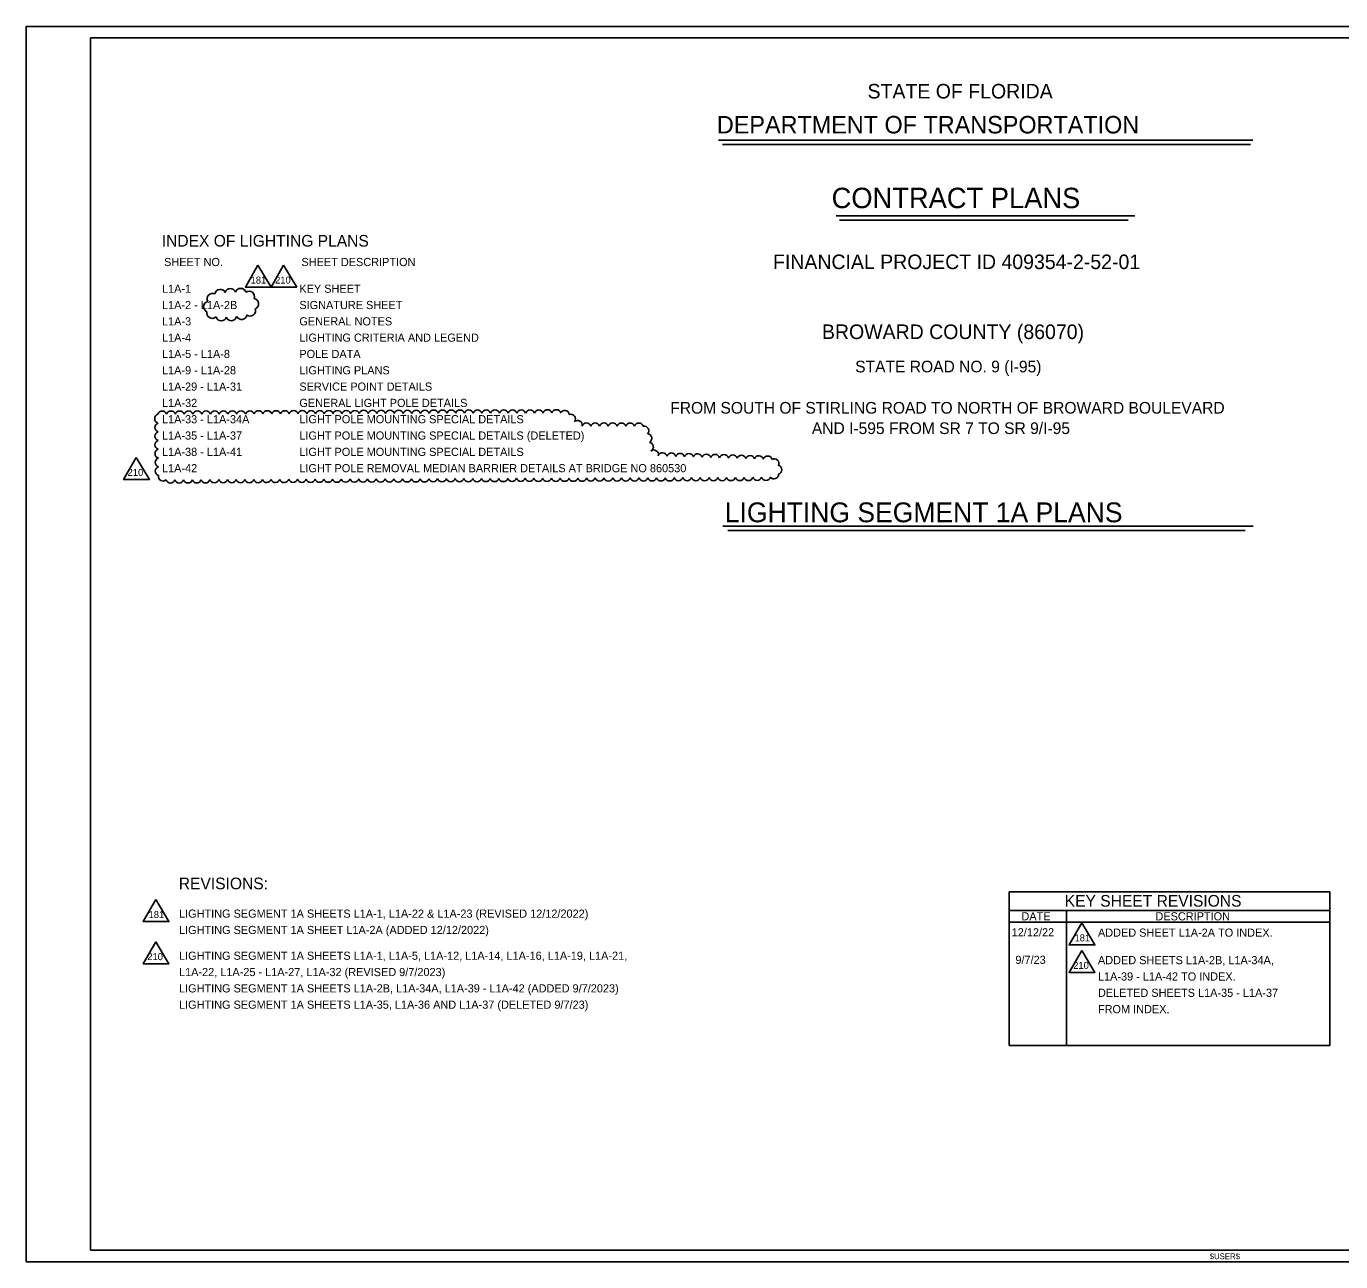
# Model space of a CAD drawing. Extents: x -820.2 to -798.1, y -2199.1 to -2182.2.
# Drawn here: x -820.23 to -808.95, y -2199.12 to -2188.52 of the extents above; entities that cross this region are included whole.
import ezdxf

# ---------------------------------------------------------------- set-up
doc = ezdxf.new("R2010")
doc.units = 0
for name, color, linetype in [('AdhocPoint_dp', 7, 'Continuous'), ('Cloud_dp', 7, 'Continuous'), ('PlotBorder_dp', 7, 'Continuous'), ('SheetBorder_dp', 7, 'Continuous'), ('SumBoxLines_dp', 7, 'Continuous'), ('TextLabel', 7, 'Continuous'), ('TextMinor', 7, 'Continuous'), ('TextNotes', 7, 'Continuous'), ('TextTitle', 7, 'Continuous')]:
    doc.layers.add(name, color=color, linetype=linetype)

msp = doc.modelspace()

# ---------------------------------------------------------------- linework, layer by layer
at = {"layer": 'AdhocPoint_dp'}
msp.add_line((-820.227, -2199.124), (-820.227, -2199.124), dxfattribs=at)
at = {"layer": 'Cloud_dp'}
for points in [[(-818.24, -2190.573), (-818.348, -2190.761), (-818.127, -2190.761)], [(-818.02, -2190.573), (-818.127, -2190.761), (-817.907, -2190.761)], [(-819.284, -2192.223), (-819.392, -2192.412), (-819.171, -2192.412)], [(-819.116, -2196.017), (-819.224, -2196.205), (-819.003, -2196.205)], [(-811.175, -2196.217), (-811.283, -2196.405), (-811.062, -2196.405)], [(-819.116, -2196.378), (-819.224, -2196.567), (-819.003, -2196.567)], [(-811.175, -2196.453), (-811.283, -2196.641), (-811.062, -2196.641)]]:
    msp.add_lwpolyline(points, close=True, dxfattribs=at)
for centre, radius, start, end in [((-818.563, -2190.827), 0.0467, 25.9096, 170.9096), ((-818.477, -2190.82), 0.0467, 18.5195, 163.5195), ((-818.388, -2190.819), 0.0467, 17.5, 162.5), ((-818.66, -2190.93), 0.0467, 103.3617, 248.3617), ((-818.63, -2190.862), 0.0467, 63.7763, 208.7763), ((-818.316, -2190.843), 0.0467, 340.504, 125.504), ((-818.281, -2190.905), 0.0467, 293.5283, 78.5283), ((-818.632, -2190.983), 0.0467, 167.6812, 312.6812), ((-818.468, -2191.003), 0.0467, 201.1358, 346.1358), ((-818.38, -2190.993), 0.0467, 205.9222, 350.9222), ((-818.307, -2190.963), 0.0467, 234.2456, 19.2456), ((-818.555, -2191.004), 0.0467, 196.176, 341.176), ((-819.086, -2191.89), 0.0394, 108.0967, 253.0967), ((-819.061, -2191.864), 0.0394, 17.6867, 162.6867), ((-818.986, -2191.864), 0.0394, 17.6867, 162.6867), ((-818.911, -2191.864), 0.0394, 17.6867, 162.6867), ((-818.835, -2191.863), 0.0394, 17.6867, 162.6867), ((-818.76, -2191.863), 0.0394, 17.6867, 162.6867), ((-818.685, -2191.863), 0.0394, 17.6867, 162.6867), ((-818.61, -2191.863), 0.0394, 17.6867, 162.6867), ((-818.535, -2191.862), 0.0394, 17.6867, 162.6867), ((-818.46, -2191.862), 0.0394, 17.6867, 162.6867), ((-818.385, -2191.862), 0.0394, 17.6867, 162.6867), ((-818.31, -2191.862), 0.0394, 17.6867, 162.6867), ((-818.235, -2191.861), 0.0394, 17.6867, 162.6867), ((-818.16, -2191.861), 0.0394, 17.6867, 162.6867), ((-818.084, -2191.861), 0.0394, 17.6867, 162.6867), ((-818.009, -2191.861), 0.0394, 17.6867, 162.6867), ((-817.934, -2191.86), 0.0394, 17.6867, 162.6867), ((-817.859, -2191.86), 0.0394, 17.6867, 162.6867), ((-817.784, -2191.86), 0.0394, 17.6867, 162.6867), ((-817.709, -2191.86), 0.0394, 17.6867, 162.6867), ((-817.634, -2191.859), 0.0394, 17.6867, 162.6867), ((-817.559, -2191.859), 0.0394, 17.6867, 162.6867), ((-817.484, -2191.859), 0.0394, 17.6867, 162.6867), ((-817.409, -2191.859), 0.0394, 17.6867, 162.6867), ((-817.333, -2191.858), 0.0394, 17.6867, 162.6867), ((-817.258, -2191.858), 0.0394, 17.6867, 162.6867), ((-817.183, -2191.858), 0.0394, 17.6867, 162.6867), ((-817.108, -2191.858), 0.0394, 17.6867, 162.6867), ((-817.033, -2191.857), 0.0394, 17.6867, 162.6867), ((-816.958, -2191.857), 0.0394, 17.6867, 162.6867), ((-816.883, -2191.857), 0.0394, 17.6867, 162.6867), ((-816.808, -2191.857), 0.0394, 17.6867, 162.6867), ((-816.733, -2191.856), 0.0394, 17.6867, 162.6867), ((-816.657, -2191.856), 0.0394, 17.6867, 162.6867), ((-816.582, -2191.856), 0.0394, 17.6867, 162.6867), ((-816.507, -2191.856), 0.0394, 17.6867, 162.6867), ((-816.432, -2191.855), 0.0394, 17.6867, 162.6867), ((-816.357, -2191.855), 0.0394, 17.6867, 162.6867), ((-816.282, -2191.855), 0.0394, 17.6867, 162.6867), ((-816.207, -2191.855), 0.0394, 17.6867, 162.6867), ((-816.132, -2191.854), 0.0394, 17.6867, 162.6867), ((-816.057, -2191.854), 0.0394, 17.6867, 162.6867), ((-815.982, -2191.854), 0.0394, 17.6867, 162.6867), ((-815.906, -2191.854), 0.0394, 17.6867, 162.6867), ((-815.831, -2191.854), 0.0394, 17.6867, 162.6867), ((-815.756, -2191.853), 0.0394, 17.6867, 162.6867), ((-815.681, -2191.853), 0.0394, 17.6867, 162.6867), ((-815.609, -2191.859), 0.0394, 7.5168, 152.5168), ((-815.557, -2191.891), 0.0393, 324.0861, 109.0861), ((-815.499, -2191.944), 0.0394, 345.7782, 130.7782), ((-819.085, -2191.965), 0.0394, 108.0967, 253.0967), ((-819.085, -2192.04), 0.0394, 108.0967, 253.0967), ((-815.423, -2191.966), 0.0394, 17.3552, 162.3552), ((-815.348, -2191.966), 0.0394, 17.3552, 162.3552), ((-815.273, -2191.966), 0.0394, 17.3552, 162.3552), ((-815.198, -2191.966), 0.0394, 17.3552, 162.3552), ((-815.123, -2191.967), 0.0394, 17.3552, 162.3552), ((-815.048, -2191.967), 0.0394, 17.3552, 162.3552), ((-814.973, -2191.967), 0.0394, 17.3552, 162.3552), ((-814.927, -2191.994), 0.0394, 317.544, 102.544), ((-814.902, -2192.059), 0.0394, 298.1939, 83.1939), ((-819.084, -2192.115), 0.0394, 108.0967, 253.0967), ((-814.888, -2192.133), 0.0394, 298.1939, 83.1939), ((-819.083, -2192.19), 0.0394, 108.0967, 253.0967), ((-819.082, -2192.265), 0.0394, 108.0967, 253.0967), ((-814.845, -2192.198), 0.0394, 344.4167, 129.4167), ((-814.77, -2192.222), 0.0394, 15.6833, 160.6833), ((-814.695, -2192.224), 0.0394, 15.6833, 160.6833), ((-814.62, -2192.227), 0.0394, 15.6833, 160.6833), ((-814.544, -2192.229), 0.0394, 15.6833, 160.6833), ((-814.469, -2192.231), 0.0394, 15.6833, 160.6833), ((-814.394, -2192.234), 0.0394, 15.6833, 160.6833), ((-814.319, -2192.236), 0.0394, 15.6833, 160.6833), ((-814.244, -2192.238), 0.0394, 15.6833, 160.6833), ((-814.169, -2192.241), 0.0394, 15.6833, 160.6833), ((-814.094, -2192.243), 0.0394, 15.6833, 160.6833), ((-814.019, -2192.246), 0.0394, 15.6833, 160.6833), ((-813.944, -2192.248), 0.0394, 15.6833, 160.6833), ((-813.869, -2192.25), 0.0394, 15.6833, 160.6833), ((-813.811, -2192.274), 0.0394, 334.9523, 119.9523), ((-819.081, -2192.34), 0.0394, 108.0967, 253.0967), ((-813.815, -2192.368), 0.0394, 218.6634, 3.6634), ((-813.787, -2192.328), 0.0394, 287.7455, 72.7455), ((-819.054, -2192.386), 0.0394, 168.0732, 313.0732), ((-818.99, -2192.403), 0.0394, 197.7455, 342.7455), ((-818.915, -2192.403), 0.0394, 197.7455, 342.7455), ((-818.84, -2192.402), 0.0394, 197.7455, 342.7455), ((-818.765, -2192.402), 0.0394, 197.7455, 342.7455), ((-818.69, -2192.402), 0.0394, 197.7455, 342.7455), ((-818.614, -2192.401), 0.0394, 197.7455, 342.7455), ((-818.539, -2192.401), 0.0394, 197.7455, 342.7455), ((-818.464, -2192.401), 0.0394, 197.7455, 342.7455), ((-818.389, -2192.4), 0.0394, 197.7455, 342.7455), ((-818.314, -2192.4), 0.0394, 197.7455, 342.7455), ((-818.239, -2192.4), 0.0394, 197.7455, 342.7455), ((-818.164, -2192.399), 0.0394, 197.7455, 342.7455), ((-818.089, -2192.399), 0.0394, 197.7455, 342.7455), ((-818.014, -2192.399), 0.0394, 197.7455, 342.7455), ((-817.939, -2192.398), 0.0394, 197.7455, 342.7455), ((-817.863, -2192.398), 0.0394, 197.7455, 342.7455), ((-817.788, -2192.398), 0.0394, 197.7455, 342.7455), ((-817.713, -2192.397), 0.0394, 197.7455, 342.7455), ((-817.638, -2192.397), 0.0394, 197.7455, 342.7455), ((-817.563, -2192.397), 0.0394, 197.7455, 342.7455), ((-817.488, -2192.396), 0.0394, 197.7455, 342.7455), ((-817.413, -2192.396), 0.0394, 197.7455, 342.7455), ((-817.338, -2192.396), 0.0394, 197.7455, 342.7455), ((-817.263, -2192.396), 0.0394, 197.7455, 342.7455), ((-817.188, -2192.395), 0.0394, 197.7455, 342.7455), ((-817.112, -2192.395), 0.0394, 197.7455, 342.7455), ((-817.037, -2192.395), 0.0394, 197.7455, 342.7455), ((-816.962, -2192.394), 0.0394, 197.7455, 342.7455), ((-816.887, -2192.394), 0.0394, 197.7455, 342.7455), ((-816.812, -2192.394), 0.0394, 197.7455, 342.7455), ((-816.737, -2192.393), 0.0394, 197.7455, 342.7455), ((-816.662, -2192.393), 0.0394, 197.7455, 342.7455), ((-816.587, -2192.393), 0.0394, 197.7455, 342.7455), ((-816.512, -2192.392), 0.0394, 197.7455, 342.7455), ((-816.436, -2192.392), 0.0394, 197.7455, 342.7455), ((-816.361, -2192.392), 0.0394, 197.7455, 342.7455), ((-816.286, -2192.391), 0.0394, 197.7455, 342.7455), ((-816.211, -2192.391), 0.0394, 197.7455, 342.7455), ((-816.136, -2192.391), 0.0394, 197.7455, 342.7455), ((-816.061, -2192.39), 0.0394, 197.7455, 342.7455), ((-815.986, -2192.39), 0.0394, 197.7455, 342.7455), ((-815.911, -2192.39), 0.0394, 197.7455, 342.7455), ((-815.836, -2192.389), 0.0394, 197.7455, 342.7455), ((-815.761, -2192.389), 0.0394, 197.7455, 342.7455), ((-815.685, -2192.389), 0.0394, 197.7455, 342.7455), ((-815.61, -2192.388), 0.0394, 197.7455, 342.7455), ((-815.535, -2192.388), 0.0394, 197.7455, 342.7455), ((-815.46, -2192.388), 0.0394, 197.7455, 342.7455), ((-815.385, -2192.387), 0.0394, 197.7455, 342.7455), ((-815.31, -2192.387), 0.0394, 197.7455, 342.7455), ((-815.235, -2192.387), 0.0394, 197.7455, 342.7455), ((-815.16, -2192.387), 0.0394, 197.7455, 342.7455), ((-815.085, -2192.386), 0.0394, 197.7455, 342.7455), ((-815.01, -2192.386), 0.0394, 197.7455, 342.7455), ((-814.934, -2192.386), 0.0394, 197.7455, 342.7455), ((-814.859, -2192.385), 0.0394, 197.7455, 342.7455), ((-814.784, -2192.385), 0.0394, 197.7455, 342.7455), ((-814.709, -2192.385), 0.0394, 197.7455, 342.7455), ((-814.634, -2192.384), 0.0394, 197.7455, 342.7455), ((-814.559, -2192.384), 0.0394, 197.7455, 342.7455), ((-814.484, -2192.384), 0.0394, 197.7455, 342.7455), ((-814.409, -2192.383), 0.0394, 197.7455, 342.7455), ((-814.334, -2192.383), 0.0394, 197.7455, 342.7455), ((-814.258, -2192.383), 0.0394, 197.7455, 342.7455), ((-814.183, -2192.382), 0.0394, 197.7455, 342.7455), ((-814.108, -2192.382), 0.0394, 197.7455, 342.7455), ((-814.033, -2192.382), 0.0394, 197.7455, 342.7455), ((-813.958, -2192.381), 0.0394, 197.7455, 342.7455), ((-813.883, -2192.381), 0.0394, 197.7455, 342.7455)]:
    msp.add_arc(centre, radius, start, end, dxfattribs=at)
at = {"layer": 'PlotBorder_dp'}
msp.add_lwpolyline([(-820.227, -2199.124), (-803.727, -2199.124), (-803.727, -2188.524), (-820.227, -2188.524)], close=True, dxfattribs=at)
at = {"layer": 'SheetBorder_dp'}
for p, q in [((-819.677, -2188.624), (-819.677, -2199.024)), ((-819.677, -2188.624), (-804.277, -2188.624)), ((-819.677, -2199.024), (-804.277, -2199.024))]:
    msp.add_line(p, q, dxfattribs=at)
at = {"layer": 'SumBoxLines_dp'}
for p, q in [((-811.796, -2195.95), (-811.796, -2197.269)), ((-811.796, -2195.95), (-809.048, -2195.95)), ((-809.048, -2195.95), (-809.048, -2197.269)), ((-811.796, -2196.11), (-809.048, -2196.11)), ((-811.306, -2196.11), (-811.306, -2197.269)), ((-811.796, -2196.21), (-809.048, -2196.21)), ((-811.796, -2197.269), (-809.048, -2197.269))]:
    msp.add_line(p, q, dxfattribs=at)
at = {"layer": 'TextTitle'}
for p, q in [((-814.289, -2189.5), (-809.707, -2189.5)), ((-814.257, -2189.538), (-809.729, -2189.538)), ((-813.281, -2190.15), (-810.719, -2190.15)), ((-813.253, -2190.188), (-810.777, -2190.188)), ((-814.252, -2192.813), (-809.704, -2192.813)), ((-814.209, -2192.851), (-809.772, -2192.851))]:
    msp.add_line(p, q, dxfattribs=at)

# ---------------------------------------------------------------- texts
at = {"layer": 'Cloud_dp'}
for s, p in [('181', (-818.303, -2190.731)), ('210', (-818.093, -2190.731)), ('210', (-819.358, -2192.381)), ('181', (-819.178, -2196.175)), ('181', (-811.237, -2196.375)), ('210', (-819.189, -2196.536)), ('210', (-811.248, -2196.611))]:
    msp.add_text(s, height=0.06, rotation=0, dxfattribs=at).set_placement(p)
at = {"layer": 'TextLabel'}
for s, height, p in [('INDEX OF LIGHTING PLANS', 0.1, (-819.065, -2190.414)), ('FINANCIAL PROJECT ID 409354-2-52-01', 0.125, (-813.823, -2190.607)), ('L1A-1', 0.07, (-819.063, -2190.81)), ('KEY SHEET', 0.07, (-817.885, -2190.81)), ('L1A-2 - L1A-2B', 0.07, (-819.063, -2190.95)), ('SIGNATURE SHEET', 0.07, (-817.885, -2190.95)), ('L1A-3', 0.07, (-819.063, -2191.09)), ('GENERAL NOTES', 0.07, (-817.885, -2191.09)), ('BROWARD COUNTY (86070)', 0.125, (-813.403, -2191.207)), ('L1A-4', 0.07, (-819.063, -2191.23)), ('LIGHTING CRITERIA AND LEGEND', 0.07, (-817.885, -2191.23)), ('L1A-5 - L1A-8', 0.07, (-819.063, -2191.37)), ('POLE DATA', 0.07, (-817.885, -2191.37)), ('L1A-9 - L1A-28', 0.07, (-819.063, -2191.51)), ('LIGHTING PLANS', 0.07, (-817.885, -2191.51)), ('STATE ROAD NO. 9 (I-95)', 0.1, (-813.118, -2191.493)), ('L1A-29 - L1A-31', 0.07, (-819.063, -2191.65)), ('SERVICE POINT DETAILS', 0.07, (-817.885, -2191.65)), ('L1A-32', 0.07, (-819.063, -2191.79)), ('GENERAL LIGHT POLE DETAILS', 0.07, (-817.885, -2191.79)), ('FROM SOUTH OF STIRLING ROAD TO NORTH OF BROWARD BOULEVARD', 0.1, (-814.704, -2191.847)), ('L1A-33 - L1A-34A', 0.07, (-819.063, -2191.93)), ('LIGHT POLE MOUNTING SPECIAL DETAILS', 0.07, (-817.885, -2191.93)), ('L1A-35 - L1A-37', 0.07, (-819.063, -2192.07)), ('LIGHT POLE MOUNTING SPECIAL DETAILS (DELETED)', 0.07, (-817.885, -2192.07)), ('AND I-595 FROM SR 7 TO SR 9/I-95', 0.1, (-813.49, -2192.022)), ('L1A-38 - L1A-41', 0.07, (-819.063, -2192.21)), ('LIGHT POLE MOUNTING SPECIAL DETAILS', 0.07, (-817.885, -2192.21)), ('L1A-42', 0.07, (-819.063, -2192.35)), ('LIGHT POLE REMOVAL MEDIAN BARRIER DETAILS AT BRIDGE NO 860530', 0.07, (-817.885, -2192.35)), ('REVISIONS:', 0.1, (-818.919, -2195.928)), ('KEY SHEET REVISIONS', 0.1, (-811.321, -2196.077))]:
    msp.add_text(s, height=height, dxfattribs=at).set_placement(p)
at = {"layer": 'TextMinor'}
for s, height, p in [('12/12/22', 0.07, (-811.776, -2196.332)), ('ADDED SHEET L1A-2A TO INDEX.', 0.07, (-811.036, -2196.335)), ('9/7/23', 0.07, (-811.744, -2196.568)), ('ADDED SHEETS L1A-2B, L1A-34A, ', 0.07, (-811.036, -2196.571)), ('L1A-39 - L1A-42 TO INDEX.', 0.07, (-811.036, -2196.711)), ('DELETED SHEETS L1A-35 - L1A-37 ', 0.07, (-811.036, -2196.851)), ('FROM INDEX.', 0.07, (-811.036, -2196.991)), ('$USER$', 0.05, (-810.078, -2199.102))]:
    msp.add_text(s, height=height, dxfattribs=at).set_placement(p)
at = {"layer": 'TextNotes'}
for s, height, p in [('SHEET NO.', 0.07, (-819.045, -2190.581)), ('SHEET DESCRIPTION', 0.07, (-817.867, -2190.581)), ('LIGHTING SEGMENT 1A SHEETS L1A-1, L1A-22 & L1A-23 (REVISED 12/12/2022)', 0.06998, (-818.917, -2196.172)), ('DATE', 0.07, (-811.692, -2196.195)), ('DESCRIPTION', 0.07, (-810.543, -2196.195)), ('LIGHTING SEGMENT 1A SHEET L1A-2A (ADDED 12/12/2022)', 0.06998, (-818.917, -2196.312)), ('LIGHTING SEGMENT 1A SHEETS L1A-1, L1A-5, L1A-12, L1A-14, L1A-16, L1A-19, L1A-21, ', 0.06998, (-818.917, -2196.533)), ('L1A-22, L1A-25 - L1A-27, L1A-32 (REVISED 9/7/2023)', 0.06998, (-818.917, -2196.673)), ('LIGHTING SEGMENT 1A SHEETS L1A-2B, L1A-34A, L1A-39 - L1A-42 (ADDED 9/7/2023)', 0.06998, (-818.917, -2196.813)), ('LIGHTING SEGMENT 1A SHEETS L1A-35, L1A-36 AND L1A-37 (DELETED 9/7/23)', 0.06998, (-818.917, -2196.953))]:
    msp.add_text(s, height=height, dxfattribs=at).set_placement(p)
at = {"layer": 'TextTitle'}
for s, height, p in [('STATE OF FLORIDA', 0.125, (-813.012, -2189.143)), ('DEPARTMENT OF TRANSPORTATION', 0.15, (-814.304, -2189.443)), ('CONTRACT PLANS', 0.175, (-813.32, -2190.084)), ('LIGHTING SEGMENT 1A PLANS', 0.17, (-814.236, -2192.779))]:
    msp.add_text(s, height=height, dxfattribs=at).set_placement(p)

doc.saveas('drawing.dxf')
